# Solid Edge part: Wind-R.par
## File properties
Title: Wind/R 54x45 cm
Author: DESYS
Template: Normal.par
Last saved by: Luca
Revision: 7
Application: Solid Edge
Tipo di contenuto documento: 0
Precisione: 0,99
Document Number: 8030/R
Revision: 0
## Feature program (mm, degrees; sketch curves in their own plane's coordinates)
sketch for "unnamed Protrusion 1" plane through (0, 0, 0) normal (0, 0, 1) x-axis (1, 0, 0)
  arc centre (0, 0) radius 0 from (0, 0) to (0, 0)
extrude "unnamed Protrusion 1" add finite 128 along -normal
sketch for "ExtrudedCutout_2" plane through (0, 0, 0) normal (0, 0, 1) x-axis (1, 0, 0)
extrude "ExtrudedCutout_2" cut finite 75 along -normal  Treatment1_DraftAngle = 20 deg
sketch for "ExtrudedProtrusion_2" plane through (0, 0, -10) normal (0, 0, 1) x-axis (1, 0, 0)
  arc centre (145.1172, -56.3333) radius 101.1537 from (193.8384, -144.9804) to (89.4877, -140.8166) cw
  arc centre (-145.1172, -56.3333) radius 101.1537 from (-193.8384, -144.9804) to (-89.4877, -140.8166) ccw
extrude "ExtrudedProtrusion_2" add finite 75 along -normal  Profile_Plane1_Distance = 10 mm; Treatment1_DraftAngle = 20 deg
sketch for "Foro_1" plane through (0, 0, 0) normal (0, 0, 1) x-axis (1, 0, 0)
  hole centre (0, 0) bore radius 25
hole "Foro_1" diameter 50 through
sketch for "ExtrudedCutout_3" plane through (0, 0, -128) normal (0, 0, -1) x-axis (1, 0, 0)
  line (-20, 164.25) -> (-20, 37.7492)
  arc centre (-40, 37.7492) radius 20 from (-25.4545, 24.0222) to (-20, 37.7492) ccw
  arc centre (40, 37.7492) radius 20 from (20, 37.7492) to (25.4545, 24.0222) ccw
  line (20, 164.25) -> (20, 37.7492)
extrude "ExtrudedCutout_3" cut finite 40 along -normal  Treatment1_DraftAngle = 20 deg
sketch for "Foro_2" plane through (0, 0, -128) normal (0, 0, -1) x-axis (-1, 0, 0)
  hole centre (240, 0) bore radius 6
hole "Foro_2" diameter 12 finite
sketch for "unnamed Hole 1" plane through (0, 0, -128) normal (0, 0, -1) x-axis (-1, 0, 0)
  hole centre (-240, 0) bore radius 6
  dimension (linear) = 240
hole "unnamed Hole 1" finite
sketch for "Foro_4" plane through (0, 0, -128) normal (0, 0, -1) x-axis (-1, 0, 0)
  hole centre (-240, 0) bore radius 8
hole "Foro_4" diameter 16 finite
sketch for "unnamed Hole 2" plane through (0, 0, -128) normal (0, 0, -1) x-axis (-1, 0, 0)
  hole centre (240, 0) bore radius 8
hole "unnamed Hole 2" finite
sketch for "unnamed RevolvedCutout 1" plane through (0, 0, 0) normal (1, 0, 0) x-axis (0, 1, 0)
  line (-192.5, -7.8293) -> (-192.5, -20)
  line (-192.5, -20) -> (-207.5, -20)
  line (-207.5, -20) -> (-207.5, -83.358)
  line (-207.5, -83.358) -> (-175, -83.358)
  line (-192.5, -7.8293) -> (-175, -7.8293)
revolve "unnamed RevolvedCutout 1" cut finite 360 deg about sketch line (-175, -7.8293) -> (-175, -83.358)
lofted cutout "unnamed LoftedCutout 1"
fillet "Rotondo_4" radius 8
fillet "Rotondo_5" radius 5
fillet "Rotondo_6" radius 10
fillet "Rotondo_7" radius 10
fillet "Rotondo_8" radius 5
fillet "Rotondo_9" radius 10
fillet "Rotondo_10" radius 7
fillet "Rotondo_13" radius 8
fillet "Rotondo_14" radius 5
sketch for "Foro_6" plane through (0, 0, 0) normal (0, -1, 0) x-axis (1, 0, 0)
hole "Foro_6" diameter 20 finite
pattern "unnamed Pattern 1" of "Foro_2", "unnamed Hole 1"
pattern "unnamed Pattern 2" of "Foro_4", "unnamed Hole 2"
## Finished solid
Body 1: solid body, 89 faces, 186 edges, 98 vertices.
  Faces by surface: blend 38, plane 15, torus 14, cylinder 12, cone 6, spline 3, swept 1
  Edges by curve: intersection 87, circle 81, line 18
Bounding box of the edges (mm; curved faces can reach further): 544.981 x 450.012 x 128.000, from (-272.5, -225.0022, -128) to (272.4805, 225.0101, 0).
Cylindrical faces by radius (mm): R5 x2, R6 x2, R7 x2, R8 x2, R10 x1, R17.5 x1, R25 x1, R32.5 x1
Conical faces (half-angle, radius in mm at the cone's reference point): 20 deg R20 x2, 20 deg R35 x1, 20 deg R101.1537 x2, 20 deg R162.7196 x1
Toroidal faces (ring radius, tube radius in mm): R0.5397 r7 x2, R22.5 r5 x1, R23.501 r5 x2, R31.499 r5 x1, R35 r10 x1, R54.4603 r7 x1, R70.4935 r10 x2, R106.7553 r8 x2, R157.1179 r8 x1, R193.3797 r10 x1
Planar faces by outward normal: +y 1, +z 3, -z 9, oblique 2
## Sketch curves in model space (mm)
line (31.2171, -165.9588, -30) -> (53, -241.1699, -30)
arc centre (0, -175, -30) radius 32.5 from (-31.2171, -165.9588, -30) through (1.9471, -142.5584, -30) to (31.2171, -165.9588, -30)
line (-53, -241.1699, -30) -> (-31.2171, -165.9588, -30)
line (-53, -241.1699, -30) -> (53, -241.1699, -30)
line (-86.468, -241.1699, -128) -> (-52.5722, -156.4305, -128)
arc centre (-6.1484, -175, -128) radius 50 from (-6.1484, -125, -128) through (-34.1798, -133.5966, -128) to (-52.5722, -156.4305, -128)
line (6.1484, -125, -128) -> (-6.1484, -125, -128)
arc centre (6.1484, -175, -128) radius 50 from (52.5722, -156.4305, -128) through (34.1798, -133.5966, -128) to (6.1484, -125, -128)
line (86.468, -241.1699, -128) -> (52.5722, -156.4305, -128)
line (86.468, -241.1699, -128) -> (-86.468, -241.1699, -128)
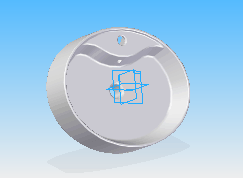
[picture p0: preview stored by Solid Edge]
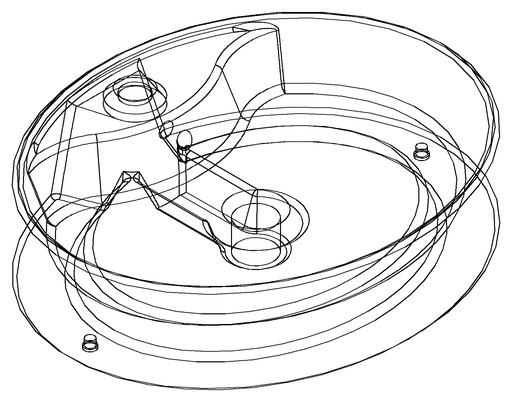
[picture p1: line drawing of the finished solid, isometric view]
